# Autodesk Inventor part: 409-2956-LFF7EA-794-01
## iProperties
Shininess: 64.0
Angle Display Precision: 2
Document Length Units: 11272
Document Angle Units: 11279
Document Time Units: 11290
Document Mass Units: 11286
Document Length Units Precision: 3
Document Angle Units Precision: 2
Compacted: True
Created: 2002-04
Part Number: 409-2956-LFF7EA-794-01
Description: 2" PIPE MOUNT ANGLE
Document SubType Name: Modeling
Designer: S. Boerckel
Mass: 2540.04 g
Surface Area: 1040.68 cm^2
Volume: 316.319 cm^3
Density: 8.03 g/cm^3
Cost Center: 3 x 3 x 1/4 ANGLE
Material: STAINLESS STEEL, 304
Engineer: S. Boerckel
User Status: SAW/PUNCH
Density: 0.0
Volumn: 0.0
Area: 0.0
PropertySet Name: Model Information
Control State: 0
Master: False
Checked Out: False
length: 13.500 in
SMR: =<COST CENTER> - <MATERIAL>
Author: S. Boerckel
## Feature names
1. Extrusion1
2. Hole1
